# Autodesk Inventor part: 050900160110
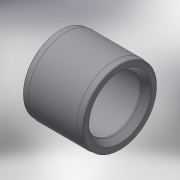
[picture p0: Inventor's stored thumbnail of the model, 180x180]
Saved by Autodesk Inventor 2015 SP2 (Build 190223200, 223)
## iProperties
Created: 2017-11
Part Number: 050900160110
Material: Generic
Description: PLASSON BUSHING-CEMENT PVC 160-110
Document SubType Name: Modeling
Designer: KIM
Density: 1 g/cm^3
Appearance: Default
Author: KIM
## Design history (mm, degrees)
derived "050900.ipt"
feature "Solid1::050900.ipt"
tag "TaggingFeature1"
body "Solid1"
other parameters: "d2" = 61, "d3" = 86, "d7" = 8.6, "d11" = 8.6, "d12" = 1.6, "d14" = 1.6, "d15" = 8.6, "d17" = 1.6, "d18" = 1.6, "d19" = 97.9, "d20" = 5, "d21" = 18.63, "L_" = 86, "l_" = 61, "z_" = 2
